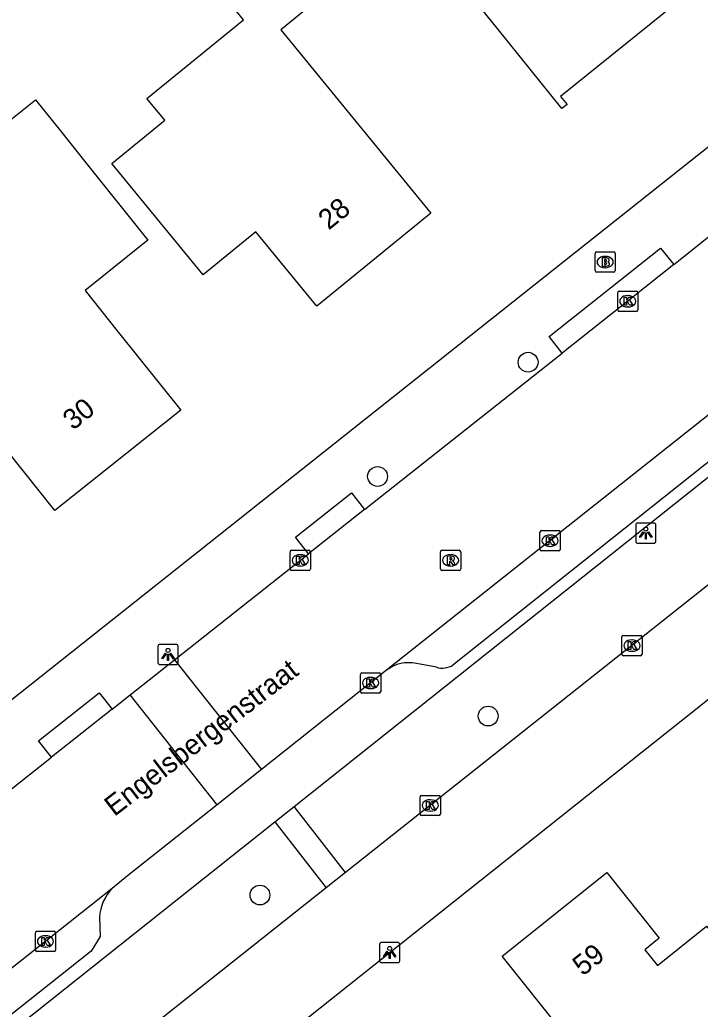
# Model space of a CAD drawing. Extents: x 159503 to 160347, y 382525 to 383272.
# Drawn here: x 159893.23 to 159926.86, y 383063.74 to 383112.66 of the extents above; entities that cross this region are included whole.
import ezdxf

# ---------------------------------------------------------------- set-up
doc = ezdxf.new("R2010")
doc.units = 0
for name, color, linetype in [('IMGEO_Boom', 7, 'Continuous'), ('IMGEO_Brandkraan', 7, 'Continuous'), ('IMGEO_Kolk', 7, 'Continuous'), ('IMGEO_Lichtpunt', 7, 'Continuous'), ('IMGEO_Openbare_ruimte_label', 7, 'Continuous'), ('IMGEO_Pand', 7, 'Continuous'), ('IMGEO_Pand_nummerreeks', 7, 'Continuous'), ('IMGEO_Rijbaan_lokaal_open', 7, 'Continuous'), ('IMGEO_Rioolput', 7, 'Continuous'), ('IMGEO_Voetpad_open', 7, 'Continuous')]:
    doc.layers.add(name, color=color, linetype=linetype)

msp = doc.modelspace()

# ---------------------------------------------------------------- linework, layer by layer
at = {"layer": 'IMGEO_Boom'}
for centre in [(159918.354, 383095.734), (159910.912, 383090.085), (159916.38, 383078.239), (159905.097, 383069.39)]:
    msp.add_circle(centre, 0.489, dxfattribs=at)
at = {"layer": 'IMGEO_Brandkraan'}
for p, q in [((159921.662, 383100.261), (159921.662, 383101.113)), ((159921.737, 383101.187), (159922.589, 383101.187)), ((159922.15, 383100.967), (159922.175, 383100.967)), ((159922.663, 383101.113), (159922.663, 383100.261)), ((159922.173, 383100.407), (159922.148, 383100.407)), ((159922.589, 383100.187), (159921.737, 383100.187))]:
    msp.add_line(p, q, dxfattribs=at)
for points in [[(159921.662, 383100.261), (159921.662, 383101.113)], [(159921.737, 383101.187), (159922.589, 383101.187)], [(159922.01, 383100.887), (159922.01, 383100.487), (159922.223, 383100.487)], [(159922.241, 383100.887), (159922.01, 383100.887)], [(159922.663, 383101.113), (159922.663, 383100.261)], [(159922.189, 383100.806), (159922.135, 383100.806), (159922.135, 383100.73)], [(159922.135, 383100.73), (159922.188, 383100.73)], [(159922.197, 383100.654), (159922.135, 383100.654), (159922.135, 383100.573)], [(159922.135, 383100.573), (159922.197, 383100.573)], [(159922.589, 383100.187), (159921.737, 383100.187)]]:
    msp.add_lwpolyline(points, dxfattribs=at)
for centre, radius, start, end in [((159921.739, 383101.111), 0.0765, 91.552, 178.448), ((159921.739, 383101.111), 0.0765, 91.552, 178.448), ((159922.245, 383100.742), 0.145, 59.4692, 91.5367), ((159922.27, 383100.789), 0.0922, 285.5137, 58.1501), ((159922.587, 383101.111), 0.0765, 1.552, 88.448), ((159922.587, 383101.111), 0.0765, 1.552, 88.448), ((159922.19, 383100.768), 0.0379, 267.8285, 90.9355), ((159922.198, 383100.613), 0.0404, 269.8759, 90.5077), ((159922.229, 383100.738), 0.251, 268.6676, 293.5347), ((159922.275, 383100.597), 0.105, 301.3115, 78.989), ((159921.739, 383100.263), 0.0765, 181.552, 268.448), ((159921.739, 383100.263), 0.0765, 181.552, 268.448), ((159922.587, 383100.263), 0.0765, 271.552, 358.448), ((159922.587, 383100.263), 0.0765, 271.552, 358.448)]:
    msp.add_arc(centre, radius, start, end, dxfattribs=at)
for centre, major_axis, ratio, start_param, end_param in [((159922.149, 383100.687), (-0.387, 0.002), 0.722429, 4.712389, 7.853982), ((159922.174, 383100.687), (-0.39, 0.002), 0.717154, 1.570796, 4.712389)]:
    msp.add_ellipse(centre, major_axis=major_axis, ratio=ratio, start_param=start_param, end_param=end_param, dxfattribs=at)
at = {"layer": 'IMGEO_Kolk'}
for p, q in [((159922.781, 383098.323), (159922.781, 383099.175)), ((159922.856, 383099.249), (159923.708, 383099.249)), ((159923.269, 383099.029), (159923.294, 383099.029)), ((159923.782, 383099.175), (159923.782, 383098.323)), ((159923.292, 383098.469), (159923.267, 383098.469)), ((159923.708, 383098.249), (159922.856, 383098.249)), ((159918.939, 383086.482), (159918.939, 383087.334)), ((159919.014, 383087.408), (159919.866, 383087.408)), ((159919.427, 383087.188), (159919.452, 383087.188)), ((159919.94, 383087.334), (159919.94, 383086.482)), ((159906.591, 383085.512), (159906.591, 383086.364)), ((159906.666, 383086.438), (159907.518, 383086.438)), ((159907.079, 383086.218), (159907.104, 383086.218)), ((159907.592, 383086.364), (159907.592, 383085.512)), ((159919.866, 383086.408), (159919.014, 383086.408)), ((159919.45, 383086.628), (159919.425, 383086.628)), ((159907.518, 383085.438), (159906.666, 383085.438)), ((159907.102, 383085.658), (159907.077, 383085.658)), ((159922.987, 383081.299), (159922.987, 383082.151)), ((159923.062, 383082.225), (159923.914, 383082.225)), ((159923.475, 383082.005), (159923.5, 383082.005)), ((159923.988, 383082.151), (159923.988, 383081.299)), ((159923.498, 383081.445), (159923.473, 383081.445)), ((159923.914, 383081.225), (159923.062, 383081.225)), ((159910.068, 383079.448), (159910.068, 383080.3)), ((159910.143, 383080.374), (159910.995, 383080.374)), ((159911.069, 383080.3), (159911.069, 383079.448)), ((159910.556, 383080.154), (159910.581, 383080.154)), ((159910.995, 383079.374), (159910.143, 383079.374)), ((159910.579, 383079.594), (159910.554, 383079.594)), ((159913.017, 383073.393), (159913.017, 383074.245)), ((159913.092, 383074.319), (159913.944, 383074.319)), ((159913.505, 383074.099), (159913.53, 383074.099)), ((159914.018, 383074.245), (159914.018, 383073.393)), ((159913.528, 383073.539), (159913.503, 383073.539)), ((159913.944, 383073.319), (159913.092, 383073.319)), ((159894.071, 383067.596), (159894.923, 383067.596)), ((159893.996, 383066.67), (159893.996, 383067.522)), ((159894.484, 383067.376), (159894.509, 383067.376)), ((159894.997, 383067.522), (159894.997, 383066.67)), ((159894.923, 383066.596), (159894.071, 383066.596)), ((159894.507, 383066.816), (159894.482, 383066.816))]:
    msp.add_line(p, q, dxfattribs=at)
for points in [[(159922.781, 383098.323), (159922.781, 383099.175)], [(159922.856, 383099.249), (159923.708, 383099.249)], [(159923.102, 383098.949), (159923.225, 383098.949), (159923.225, 383098.798), (159923.355, 383098.949), (159923.519, 383098.949), (159923.373, 383098.798), (159923.526, 383098.549), (159923.374, 383098.549), (159923.289, 383098.713), (159923.225, 383098.646), (159923.225, 383098.549), (159923.102, 383098.549), (159923.102, 383098.949)], [(159923.782, 383099.175), (159923.782, 383098.323)], [(159923.708, 383098.249), (159922.856, 383098.249)], [(159918.939, 383086.482), (159918.939, 383087.334)], [(159919.014, 383087.408), (159919.866, 383087.408)], [(159919.94, 383087.334), (159919.94, 383086.482)], [(159919.26, 383087.108), (159919.383, 383087.108), (159919.383, 383086.957), (159919.513, 383087.108), (159919.677, 383087.108), (159919.531, 383086.957), (159919.684, 383086.708), (159919.532, 383086.708), (159919.447, 383086.872), (159919.383, 383086.805), (159919.383, 383086.708), (159919.26, 383086.708), (159919.26, 383087.108)], [(159906.591, 383085.512), (159906.591, 383086.364)], [(159906.666, 383086.438), (159907.518, 383086.438)], [(159907.592, 383086.364), (159907.592, 383085.512)], [(159919.866, 383086.408), (159919.014, 383086.408)], [(159906.912, 383086.138), (159907.035, 383086.138), (159907.035, 383085.987), (159907.165, 383086.138), (159907.329, 383086.138), (159907.183, 383085.987), (159907.336, 383085.738), (159907.184, 383085.738), (159907.099, 383085.902), (159907.035, 383085.835), (159907.035, 383085.738), (159906.912, 383085.738), (159906.912, 383086.138)], [(159907.518, 383085.438), (159906.666, 383085.438)], [(159922.987, 383081.299), (159922.987, 383082.151)], [(159923.062, 383082.225), (159923.914, 383082.225)], [(159923.308, 383081.925), (159923.431, 383081.925), (159923.431, 383081.774), (159923.561, 383081.925), (159923.725, 383081.925), (159923.579, 383081.774), (159923.732, 383081.525), (159923.58, 383081.525), (159923.495, 383081.689), (159923.431, 383081.622), (159923.431, 383081.525), (159923.308, 383081.525), (159923.308, 383081.925)], [(159923.988, 383082.151), (159923.988, 383081.299)], [(159923.914, 383081.225), (159923.062, 383081.225)], [(159910.068, 383079.448), (159910.068, 383080.3)], [(159910.143, 383080.374), (159910.995, 383080.374)], [(159911.069, 383080.3), (159911.069, 383079.448)], [(159910.389, 383080.074), (159910.512, 383080.074), (159910.512, 383079.923), (159910.642, 383080.074), (159910.806, 383080.074), (159910.66, 383079.923), (159910.813, 383079.674), (159910.661, 383079.674), (159910.576, 383079.838), (159910.512, 383079.771), (159910.512, 383079.674), (159910.389, 383079.674), (159910.389, 383080.074)], [(159910.995, 383079.374), (159910.143, 383079.374)], [(159913.017, 383073.393), (159913.017, 383074.245)], [(159913.092, 383074.319), (159913.944, 383074.319)], [(159913.338, 383074.019), (159913.461, 383074.019), (159913.461, 383073.868), (159913.591, 383074.019), (159913.755, 383074.019), (159913.609, 383073.868), (159913.762, 383073.619), (159913.61, 383073.619), (159913.525, 383073.783), (159913.461, 383073.716), (159913.461, 383073.619), (159913.338, 383073.619), (159913.338, 383074.019)], [(159914.018, 383074.245), (159914.018, 383073.393)], [(159913.944, 383073.319), (159913.092, 383073.319)], [(159894.071, 383067.596), (159894.923, 383067.596)], [(159893.996, 383066.67), (159893.996, 383067.522)], [(159894.317, 383067.296), (159894.44, 383067.296), (159894.44, 383067.145), (159894.57, 383067.296), (159894.734, 383067.296), (159894.588, 383067.145), (159894.741, 383066.896), (159894.589, 383066.896), (159894.504, 383067.06), (159894.44, 383066.993), (159894.44, 383066.896), (159894.317, 383066.896), (159894.317, 383067.296)], [(159894.997, 383067.522), (159894.997, 383066.67)], [(159894.923, 383066.596), (159894.071, 383066.596)]]:
    msp.add_lwpolyline(points, dxfattribs=at)
for centre, start, end in [((159922.858, 383099.173), 91.552, 178.448), ((159922.858, 383099.173), 91.552, 178.448), ((159923.706, 383099.173), 1.552, 88.448), ((159923.706, 383099.173), 1.552, 88.448), ((159922.858, 383098.325), 181.552, 268.448), ((159922.858, 383098.325), 181.552, 268.448), ((159923.706, 383098.325), 271.552, 358.448), ((159923.706, 383098.325), 271.552, 358.448), ((159919.016, 383087.332), 91.552, 178.448), ((159919.016, 383087.332), 91.552, 178.448), ((159919.864, 383087.332), 1.552, 88.448), ((159919.864, 383087.332), 1.552, 88.448), ((159906.668, 383086.362), 91.552, 178.448), ((159906.668, 383086.362), 91.552, 178.448), ((159907.516, 383086.362), 1.552, 88.448), ((159907.516, 383086.362), 1.552, 88.448), ((159919.016, 383086.484), 181.552, 268.448), ((159919.016, 383086.484), 181.552, 268.448), ((159919.864, 383086.484), 271.552, 358.448), ((159919.864, 383086.484), 271.552, 358.448), ((159906.668, 383085.514), 181.552, 268.448), ((159906.668, 383085.514), 181.552, 268.448), ((159907.516, 383085.514), 271.552, 358.448), ((159907.516, 383085.514), 271.552, 358.448), ((159923.064, 383082.149), 91.552, 178.448), ((159923.064, 383082.149), 91.552, 178.448), ((159923.912, 383082.149), 1.552, 88.448), ((159923.912, 383082.149), 1.552, 88.448), ((159923.064, 383081.301), 181.552, 268.448), ((159923.064, 383081.301), 181.552, 268.448), ((159923.912, 383081.301), 271.552, 358.448), ((159923.912, 383081.301), 271.552, 358.448), ((159910.145, 383080.298), 91.552, 178.448), ((159910.145, 383080.298), 91.552, 178.448), ((159910.993, 383080.298), 1.552, 88.448), ((159910.993, 383080.298), 1.552, 88.448), ((159910.145, 383079.45), 181.552, 268.448), ((159910.145, 383079.45), 181.552, 268.448), ((159910.993, 383079.45), 271.552, 358.448), ((159910.993, 383079.45), 271.552, 358.448), ((159913.094, 383074.243), 91.552, 178.448), ((159913.094, 383074.243), 91.552, 178.448), ((159913.942, 383074.243), 1.552, 88.448), ((159913.942, 383074.243), 1.552, 88.448), ((159913.094, 383073.395), 181.552, 268.448), ((159913.094, 383073.395), 181.552, 268.448), ((159913.942, 383073.395), 271.552, 358.448), ((159913.942, 383073.395), 271.552, 358.448), ((159894.073, 383067.52), 91.552, 178.448), ((159894.073, 383067.52), 91.552, 178.448), ((159894.921, 383067.52), 1.552, 88.448), ((159894.921, 383067.52), 1.552, 88.448), ((159894.073, 383066.672), 181.552, 268.448), ((159894.073, 383066.672), 181.552, 268.448), ((159894.921, 383066.672), 271.552, 358.448), ((159894.921, 383066.672), 271.552, 358.448)]:
    msp.add_arc(centre, 0.0765, start, end, dxfattribs=at)
for centre, major_axis, ratio, start_param, end_param in [((159923.268, 383098.749), (-0.387, 0.002), 0.722429, 4.712389, 7.853982), ((159923.293, 383098.749), (-0.39, 0.002), 0.717154, 1.570796, 4.712389), ((159919.426, 383086.908), (-0.387, 0.002), 0.722429, 4.712389, 7.853982), ((159919.451, 383086.908), (-0.39, 0.002), 0.717154, 1.570796, 4.712389), ((159907.078, 383085.938), (-0.387, 0.002), 0.722429, 4.712389, 7.853982), ((159907.103, 383085.938), (-0.39, 0.002), 0.717154, 1.570796, 4.712389), ((159923.474, 383081.725), (-0.387, 0.002), 0.722429, 4.712389, 7.853982), ((159923.499, 383081.725), (-0.39, 0.002), 0.717154, 1.570796, 4.712389), ((159910.555, 383079.874), (-0.387, 0.002), 0.722429, 4.712389, 7.853982), ((159910.58, 383079.874), (-0.39, 0.002), 0.717154, 1.570796, 4.712389), ((159913.504, 383073.819), (-0.387, 0.002), 0.722429, 4.712389, 7.853982), ((159913.529, 383073.819), (-0.39, 0.002), 0.717154, 1.570796, 4.712389), ((159894.483, 383067.096), (-0.387, 0.002), 0.722429, 4.712389, 7.853982), ((159894.508, 383067.096), (-0.39, 0.002), 0.717154, 1.570796, 4.712389)]:
    msp.add_ellipse(centre, major_axis=major_axis, ratio=ratio, start_param=start_param, end_param=end_param, dxfattribs=at)
at = {"layer": 'IMGEO_Lichtpunt'}
for p, q in [((159923.673, 383087.688), (159923.673, 383086.881)), ((159923.673, 383087.688), (159923.673, 383086.881)), ((159924.575, 383087.783), (159923.767, 383087.783)), ((159924.575, 383087.783), (159923.767, 383087.783)), ((159924.669, 383086.881), (159924.669, 383087.688)), ((159924.669, 383086.881), (159924.669, 383087.688)), ((159923.767, 383086.787), (159924.575, 383086.787)), ((159923.767, 383086.787), (159924.575, 383086.787)), ((159900.96, 383081.782), (159900.152, 383081.782)), ((159900.96, 383081.782), (159900.152, 383081.782)), ((159900.058, 383081.687), (159900.058, 383080.88)), ((159900.058, 383081.687), (159900.058, 383080.88)), ((159901.054, 383080.88), (159901.054, 383081.687)), ((159901.054, 383080.88), (159901.054, 383081.687)), ((159900.152, 383080.786), (159900.96, 383080.786)), ((159900.152, 383080.786), (159900.96, 383080.786)), ((159911.012, 383066.951), (159911.012, 383066.144)), ((159911.012, 383066.951), (159911.012, 383066.144)), ((159911.914, 383067.046), (159911.106, 383067.046)), ((159911.914, 383067.046), (159911.106, 383067.046)), ((159912.008, 383066.144), (159912.008, 383066.951)), ((159912.008, 383066.144), (159912.008, 383066.951)), ((159911.106, 383066.05), (159911.914, 383066.05)), ((159911.106, 383066.05), (159911.914, 383066.05))]:
    msp.add_line(p, q, dxfattribs=at)
for points in [[(159924.047, 383087.352), (159924.086, 383087.324), (159923.898, 383087.062), (159923.86, 383087.089), (159924.047, 383087.352)], [(159924.149, 383087.304), (159924.196, 383087.304), (159924.196, 383086.982), (159924.149, 383086.982), (159924.149, 383087.304)], [(159924.259, 383087.324), (159924.297, 383087.351), (159924.484, 383087.089), (159924.445, 383087.061), (159924.259, 383087.324)], [(159900.432, 383081.351), (159900.471, 383081.323), (159900.283, 383081.061), (159900.245, 383081.088), (159900.432, 383081.351)], [(159900.534, 383081.303), (159900.581, 383081.303), (159900.581, 383080.981), (159900.534, 383080.981), (159900.534, 383081.303)], [(159900.644, 383081.323), (159900.682, 383081.35), (159900.869, 383081.088), (159900.83, 383081.06), (159900.644, 383081.323)], [(159911.386, 383066.615), (159911.425, 383066.587), (159911.237, 383066.325), (159911.199, 383066.352), (159911.386, 383066.615)], [(159911.598, 383066.587), (159911.636, 383066.614), (159911.823, 383066.352), (159911.784, 383066.324), (159911.598, 383066.587)], [(159911.488, 383066.567), (159911.535, 383066.567), (159911.535, 383066.245), (159911.488, 383066.245), (159911.488, 383066.567)]]:
    msp.add_lwpolyline(points, dxfattribs=at)
for centre in [(159924.172, 383087.486), (159900.557, 383081.485), (159911.511, 383066.749)]:
    msp.add_circle(centre, 0.0994, dxfattribs=at)
for centre, start, end in [((159923.767, 383087.688), 90, 180), ((159923.767, 383087.688), 90, 180), ((159924.575, 383087.688), 0, 90), ((159924.575, 383087.688), 0, 90), ((159923.767, 383086.881), 180, 270), ((159923.767, 383086.881), 180, 270), ((159924.575, 383086.881), 270, 0), ((159924.575, 383086.881), 270, 360), ((159900.152, 383081.687), 90, 180), ((159900.152, 383081.687), 90, 180), ((159900.96, 383081.687), 0, 90), ((159900.96, 383081.687), 0, 90), ((159900.152, 383080.88), 180, 270), ((159900.152, 383080.88), 180, 270), ((159900.96, 383080.88), 270, 0), ((159900.96, 383080.88), 270, 360), ((159911.106, 383066.951), 90, 180), ((159911.106, 383066.951), 90, 180), ((159911.914, 383066.951), 0, 90), ((159911.914, 383066.951), 0, 90), ((159911.106, 383066.144), 180, 270), ((159911.106, 383066.144), 180, 270), ((159911.914, 383066.144), 270, 0), ((159911.914, 383066.144), 270, 360)]:
    msp.add_arc(centre, 0.0946, start, end, dxfattribs=at)
at = {"layer": 'IMGEO_Pand'}
for points in [[(159913.547, 383135.857), (159920.78, 383126.811), (159923.903, 383122.906), (159920.632, 383120.268), (159926.282, 383113.262), (159926.056, 383113.08), (159925.71, 383113.509), (159919.963, 383108.875), (159920.279, 383108.484), (159920.027, 383108.28), (159916.888, 383112.173), (159912.821, 383117.217), (159915.894, 383119.695), (159915.438, 383120.26), (159918.447, 383122.686), (159910.081, 383133.062), (159913.547, 383135.857)], [(159903.249, 383122.778), (159906.394, 383118.846), (159909.516, 383114.941), (159906.132, 383112.173), (159913.546, 383103.109), (159907.915, 383098.503), (159904.901, 383102.188), (159902.293, 383100.054), (159897.785, 383105.565), (159900.394, 383107.699), (159899.515, 383108.774), (159904.278, 383112.669), (159898.911, 383119.23), (159903.249, 383122.778)], [(159896.435, 383105.666), (159899.558, 383101.761), (159896.456, 383099.282), (159898.049, 383097.29), (159901.186, 383093.367), (159894.968, 383088.395), (159891.845, 383092.3), (159888.958, 383095.91), (159891.873, 383098.241), (159892.029, 383098.366), (159889, 383102.154), (159890.953, 383103.715), (159889.704, 383105.277), (159894, 383108.712), (159895.234, 383107.168), (159896.435, 383105.666)], [(159937.475, 383059.76), (159935.132, 383057.887), (159931.423, 383062.527), (159928.167, 383059.923), (159927.753, 383059.087), (159926.961, 383058.405), (159926.066, 383058.258), (159922.824, 383055.666), (159922.187, 383056.462), (159919.064, 383060.367), (159921.485, 383062.302), (159920.86, 383063.083), (159920.149, 383062.514), (159917.07, 383066.364), (159922.239, 383070.497), (159924.831, 383067.256), (159924.121, 383066.688), (159924.746, 383065.907), (159927.168, 383067.843), (159927.899, 383066.93), (159930.243, 383068.804), (159933.366, 383064.899), (159937.475, 383059.76)]]:
    msp.add_lwpolyline(points, dxfattribs=at)
at = {"layer": 'IMGEO_Rijbaan_lokaal_open'}
for points in [[(159925.553, 383100.562), (159944.715, 383115.876)], [(159950.297, 383111.374), (159911.357, 383080.502)], [(159961.699, 383106.426), (159884.908, 383045.395), (159855.273, 383021.828)], [(159925.553, 383100.562), (159923.387, 383098.831), (159920.045, 383096.187)], [(159910.271, 383088.453), (159920.045, 383096.187)], [(159934.146, 383090.179), (159909.329, 383070.5)], [(159910.271, 383088.453), (159907.499, 383086.26)], [(159900.872, 383081.016), (159907.499, 383086.26)], [(159898.684, 383079.284), (159900.872, 383081.016)], [(159900.872, 383081.016), (159905.174, 383075.589)], [(159911.357, 383080.502), (159905.174, 383075.589)], [(159897.791, 383078.578), (159898.684, 383079.284)], [(159902.989, 383073.853), (159898.684, 383079.284)], [(159897.791, 383078.578), (159894.8, 383076.206)], [(159883.119, 383066.94), (159894.8, 383076.206)], [(159905.174, 383075.589), (159902.989, 383073.853)], [(159902.989, 383073.853), (159898.558, 383070.332), (159897.799, 383069.718)], [(159909.329, 383070.5), (159908.378, 383069.746)], [(159897.799, 383069.718), (159860.512, 383040.122)], [(159908.378, 383069.746), (159884.082, 383050.481)]]:
    msp.add_lwpolyline(points, dxfattribs=at)
at = {"layer": 'IMGEO_Rioolput'}
for p, q in [((159914.021, 383085.512), (159914.021, 383086.364)), ((159914.096, 383086.438), (159914.948, 383086.438)), ((159914.509, 383086.218), (159914.534, 383086.218)), ((159915.022, 383086.364), (159915.022, 383085.512)), ((159914.948, 383085.438), (159914.096, 383085.438)), ((159914.532, 383085.658), (159914.507, 383085.658))]:
    msp.add_line(p, q, dxfattribs=at)
for points in [[(159914.021, 383085.512), (159914.021, 383086.364)], [(159914.096, 383086.438), (159914.948, 383086.438)], [(159915.022, 383086.364), (159915.022, 383085.512)], [(159914.61, 383086.136), (159914.358, 383086.138), (159914.358, 383085.738)], [(159914.358, 383085.738), (159914.482, 383085.738), (159914.482, 383085.9), (159914.493, 383085.9)], [(159914.536, 383086.057), (159914.482, 383086.057), (159914.482, 383085.976)], [(159914.482, 383085.976), (159914.534, 383085.976)], [(159914.54, 383085.871), (159914.611, 383085.738), (159914.751, 383085.738), (159914.686, 383085.864)], [(159914.948, 383085.438), (159914.096, 383085.438)]]:
    msp.add_lwpolyline(points, dxfattribs=at)
for centre, radius, start, end in [((159914.098, 383086.362), 0.0765, 91.552, 178.448), ((159914.098, 383086.362), 0.0765, 91.552, 178.448), ((159914.946, 383086.362), 0.0765, 1.552, 88.448), ((159914.946, 383086.362), 0.0765, 1.552, 88.448), ((159914.492, 383085.847), 0.0533, 26.0293, 88.6989), ((159914.518, 383086.165), 0.19, 274.7715, 282.9687), ((159914.542, 383085.961), 0.0964, 77.0061, 93.1865), ((159914.556, 383086.018), 0.0378, 276.6634, 79.6772), ((159914.609, 383086.026), 0.109, 350.3612, 89.416), ((159914.607, 383086.026), 0.112, 277.5842, 350.9817), ((159914.591, 383085.811), 0.108, 29.5134, 73.7905), ((159914.098, 383085.514), 0.0765, 181.552, 268.448), ((159914.098, 383085.514), 0.0765, 181.552, 268.448), ((159914.946, 383085.514), 0.0765, 271.552, 358.448), ((159914.946, 383085.514), 0.0765, 271.552, 358.448)]:
    msp.add_arc(centre, radius, start, end, dxfattribs=at)
for centre, major_axis, ratio, start_param, end_param in [((159914.508, 383085.938), (-0.387, 0.002), 0.722429, 4.712389, 7.853982), ((159914.533, 383085.938), (-0.39, 0.002), 0.717154, 1.570796, 4.712389)]:
    msp.add_ellipse(centre, major_axis=major_axis, ratio=ratio, start_param=start_param, end_param=end_param, dxfattribs=at)
at = {"layer": 'IMGEO_Voetpad_open'}
for points in [[(159838.776, 383036.162), (160000, 383164.155), (160003.86, 383167.245)], [(159949.26, 383108.299), (159914.641, 383080.756)], [(159920.045, 383096.187), (159919.398, 383097.001), (159924.906, 383101.376), (159925.553, 383100.562)], [(159906.787, 383073.771), (159931.545, 383093.463), (159934.146, 383090.179)], [(159907.499, 383086.26), (159906.854, 383087.076), (159909.626, 383089.269), (159910.271, 383088.453)], [(159913.819, 383080.651), (159912.832, 383080.836)], [(159894.8, 383076.206), (159894.154, 383077.021), (159897.145, 383079.393), (159897.791, 383078.578)], [(159905.827, 383073.006), (159906.787, 383073.771)], [(159909.329, 383070.5), (159906.787, 383073.771)], [(159884.082, 383050.481), (159881.522, 383053.674), (159905.827, 383073.006)], [(159905.827, 383073.006), (159908.378, 383069.746)], [(159897.168, 383068.294), (159897.198, 383067.344), (159896.761, 383066.609), (159863.615, 383040.328)]]:
    msp.add_lwpolyline(points, dxfattribs=at)
for centre, radius, start, end in [((159912.451, 383079.094), 1.784, 77.6733, 127.8446), ((159914.106, 383081.673), 1.061, 254.3, 300.2588), ((159899.391, 383068.161), 2.227, 135.6366, 176.5654)]:
    msp.add_arc(centre, radius, start, end, dxfattribs=at)

# ---------------------------------------------------------------- texts
at = {"layer": 'IMGEO_Openbare_ruimte_label'}
msp.add_text('Engelsbergenstraat', height=1, rotation=37.6489, dxfattribs=at).set_placement((159897.903, 383073.244))
at = {"layer": 'IMGEO_Pand_nummerreeks'}
for s, rotation, p in [('28', 39.2822, (159908.497, 383102.235)), ('30', 38.6463, (159895.86, 383092.335)), ('59', 38.6449, (159921.058, 383065.353))]:
    msp.add_text(s, height=1, rotation=rotation, dxfattribs=at).set_placement(p)

doc.saveas('drawing.dxf')
